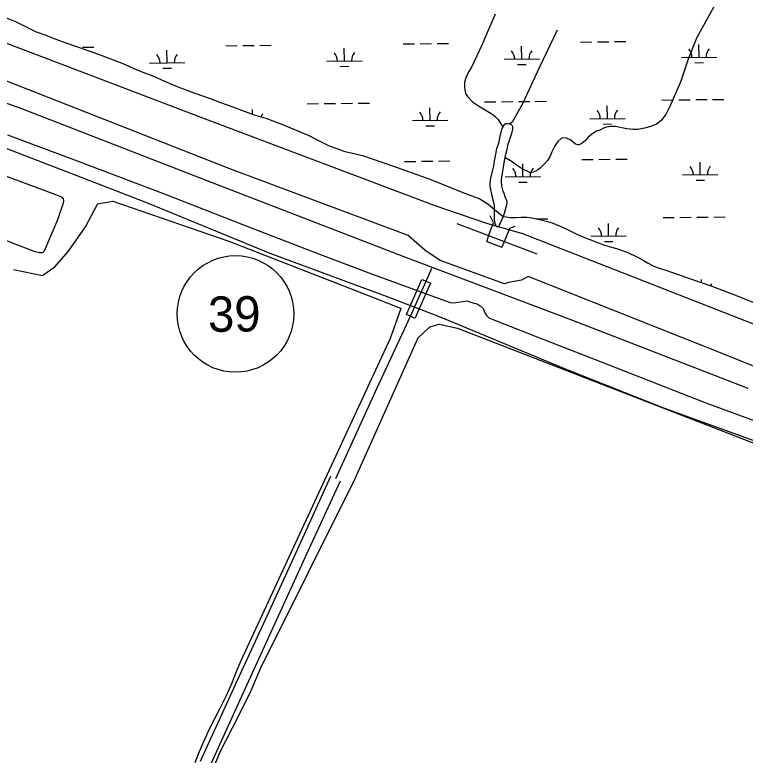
# Model space of a CAD drawing. Extents: x 3734862 to 3772949, y 391520 to 417239.
# Drawn here: x 3742033 to 3744100, y 410402 to 412498 of the extents above; entities that cross this region are included whole.
import ezdxf

# ---------------------------------------------------------------- set-up
doc = ezdxf.new("R2010")
doc.units = 0
for name, color, linetype in [('V-BRDG-OTLN', 7, 'Continuous'), ('V-LEVE-TOET', 7, 'Continuous'), ('V-ROAD-CNTR', 7, 'Continuous'), ('V-ROAD-IDEN', 7, 'Continuous'), ('V-RRAP-FSHR', 7, 'Continuous'), ('V-SITE-VEGE', 7, 'Continuous'), ('V-TOPO-SHOR', 7, 'Continuous'), ('V-TRAN-LOCK', 7, 'Continuous'), ('V-WETL-SWMP', 7, 'Continuous')]:
    doc.layers.add(name, color=color, linetype=linetype)

msp = doc.modelspace()

# ---------------------------------------------------------------- linework, layer by layer
at = {"layer": 'V-BRDG-OTLN'}
msp.add_line((3743152.4, 411644.3), (3743197.4, 411743.5), dxfattribs=at)
msp.add_lwpolyline([(3743165.3, 411638.4), (3743152.4, 411644.3), (3743141.2, 411649.6), (3743184.9, 411748.9), (3743197.4, 411743.5), (3743209.5, 411738.2)], close=True, dxfattribs=at)
at = {"layer": 'V-LEVE-TOET'}
msp.add_line((3743367.5, 411908.1), (3743469.8, 411878.6), dxfattribs=at)
for points in [[(3738852.9, 413396.4), (3739138.4, 413315.6), (3740264.7, 412984.9), (3741306.9, 412677.6), (3741416.7, 412646.4), (3741439.2, 412637.7), (3741731.3, 412522.7), (3742578.6, 412200.2), (3743221.3, 411958.2), (3743367.5, 411908.1)], [(3744926.8, 411188.3), (3744890.4, 411207.3), (3744850.8, 411205.9), (3744810.7, 411224.9), (3744044.1, 411535), (3743485.6, 411757.3), (3743467, 411746.5), (3743430.2, 411739.8), (3743419.1, 411736.3), (3743236.4, 411801.8), (3743192.8, 411831.9), (3743145.7, 411873.1), (3742641.7, 412061.3), (3741586.5, 412475.4), (3741466, 412517.8), (3741404.7, 412536.6), (3741298.7, 412571.4), (3740527, 412789.8), (3739719, 413038.2), (3738899.6, 413268.3), (3738854.4, 413281.1)], [(3743469.8, 411878.6), (3744276.8, 411562.5), (3744864.5, 411325.1), (3744898.6, 411320.1), (3745007.8, 411297.3)]]:
    msp.add_lwpolyline(points, dxfattribs=at)
at = {"layer": 'V-ROAD-CNTR'}
for points in [[(3738852, 413216.3), (3739597.6, 412997), (3740128.2, 412846.1), (3740911.5, 412622.8), (3741371.7, 412476), (3742051.4, 412232), (3742605.7, 412017.1), (3743130.7, 411814.9), (3743608.3, 411634.1), (3744107.4, 411440.8)], [(3742941.2, 411185.1), (3742994, 411301.1), (3743064.2, 411454.1), (3743135.4, 411608.1), (3743152.4, 411644.3), (3743197.4, 411743.5), (3743213.2, 411780.1)], [(3742557.9, 410384.9), (3742657.3, 410602.2), (3742747.4, 410798.6), (3742838, 410996.9), (3742927.5, 411191.4)], [(3742585.2, 410372.5), (3742684.6, 410589.7), (3742774.6, 410786.1), (3742865.3, 410984.4), (3742954.8, 411178.9)]]:
    msp.add_lwpolyline(points, dxfattribs=at)
at = {"layer": 'V-ROAD-IDEN'}
msp.add_circle((3742657.4, 411650.9), 165, dxfattribs=at)
msp.add_circle((3742657.4, 411650.9), 165, dxfattribs=at)
at = {"layer": 'V-RRAP-FSHR'}
for points in [[(3743368.4, 411856.4), (3743375.5, 411876.7), (3743387.2, 411909.6), (3743378.2, 411928.5)], [(3743283.6, 411907.2), (3743510.1, 411820.7)], [(3743448.3, 411898.2), (3743432.7, 411892.6), (3743419.3, 411859.7), (3743411.2, 411840.1)]]:
    msp.add_lwpolyline(points, dxfattribs=at)
at = {"layer": 'V-SITE-VEGE'}
for points in [[(3742029.4, 411776.3), (3742111.1, 411760.1), (3742111.8, 411760.3), (3742146.1, 411784.4), (3742184.9, 411828.9), (3742232.3, 411897.6), (3742266.6, 411962), (3742267.1, 411962.5), (3742309.7, 411970.5), (3742310.2, 411970.4), (3742638, 411857.2), (3743052.2, 411695.3), (3743124.7, 411667.3), (3743125.2, 411666.9), (3743125.3, 411666.1), (3743095.4, 411581.9), (3742672.5, 410669.4)], [(3742597, 410370), (3742612.5, 410409.4), (3742667.1, 410514.2), (3742701.8, 410585.6), (3742729, 410649), (3742996.1, 411185.3), (3743173, 411581.8), (3743173.2, 411582.1), (3743207.4, 411614.2), (3743207.8, 411614.4), (3743233.2, 411622.4), (3743233.8, 411622.4), (3743285.3, 411610.3), (3746427, 410392)], [(3742672.5, 410669.4), (3742661.4, 410642.5), (3742652.4, 410621.5), (3742645.9, 410604.5), (3742631.1, 410570.3), (3742624.3, 410556.6), (3742611.7, 410532.4), (3742583.8, 410477.3), (3742575.1, 410459.2), (3742565.5, 410437.9), (3742551.9, 410405.4), (3742541.8, 410380.5)]]:
    msp.add_lwpolyline(points, dxfattribs=at)
at = {"layer": 'V-TOPO-SHOR'}
for points in [[(3738856.9, 413083.7), (3739161.6, 412995.9), (3739452.4, 412912.1), (3739705.5, 412839.6), (3740003.1, 412755.6), (3740393.5, 412645.8), (3740671.5, 412564.1), (3740972.5, 412480.8), (3741257.8, 412388.9), (3741438.8, 412334.5), (3741752.7, 412215.1), (3741995.4, 412125.2), (3742217.9, 412039.1), (3742410.1, 411964.3), (3742754, 411823.4), (3743083.5, 411701.7), (3743238, 411641.7), (3743590.1, 411495.3), (3743868.3, 411385.2), (3744209.8, 411261.9), (3744443, 411170.9), (3744579.1, 411127.5)], [(3744015.7, 412528.2), (3743963.1, 412433.4), (3743938.8, 412371.6), (3743917.3, 412310.1), (3743909.1, 412290.2), (3743895.7, 412259.5), (3743886.3, 412238), (3743875.2, 412215.6), (3743861.2, 412197.5), (3743849.3, 412187.7), (3743833.1, 412181.1), (3743814.7, 412176.3), (3743795.6, 412173.3), (3743782.1, 412172.7), (3743765.1, 412174.6), (3743750.3, 412177.8), (3743742.7, 412179.5), (3743731.6, 412181.2), (3743718.3, 412181.2), (3743707.7, 412180), (3743698.8, 412176.5), (3743688.2, 412171.5), (3743679.3, 412167.8), (3743665.9, 412159.8), (3743654.9, 412150), (3743648.6, 412142.6), (3743638.4, 412134.2), (3743630.1, 412129.6), (3743626.4, 412129.1), (3743620, 412131.2), (3743611.7, 412137.6), (3743604.3, 412143.4), (3743593.7, 412148.4), (3743586.6, 412149.1), (3743579.2, 412147.5), (3743569.4, 412138.8), (3743559.8, 412124.9), (3743552.9, 412109.9), (3743546.6, 412095.8), (3743540.4, 412085.3), (3743532, 412076.2), (3743519.7, 412063.9), (3743512.9, 412059.1), (3743506.6, 412055.1), (3743499.5, 412052.1), (3743495.8, 412051.2), (3743490.3, 412051.7), (3743468.4, 412061.4), (3743448.4, 412075.2), (3743437.6, 412083.3), (3743419.6, 412093.7)], [(3743392.5, 412499.4), (3743370.5, 412449), (3743355.2, 412413.8), (3743324.8, 412349.4), (3743314.9, 412332.7), (3743308, 412316.1), (3743305.8, 412305.6), (3743305.2, 412290.9), (3743308.3, 412275.2), (3743314.2, 412265.9), (3743328.1, 412251.5), (3743345.1, 412239.7), (3743359.1, 412231.2), (3743385.3, 412215.5), (3743392.9, 412209.1), (3743401, 412200.8), (3743414.4, 412180)], [(3743567.3, 412453.7), (3743516.8, 412347.1), (3743469.9, 412245.5), (3743440.7, 412193.9), (3743433.9, 412188.5)], [(3743390.2, 411946.1), (3743390, 411958.1), (3743387.9, 411970.1), (3743385, 411980.2), (3743382.4, 411990.2), (3743380, 412003.4), (3743378.5, 412012.7), (3743378.4, 412020.9), (3743379.1, 412029.8), (3743380.8, 412039.8), (3743388.3, 412068.8), (3743390.4, 412083.8), (3743392.8, 412097.8), (3743394.7, 412109), (3743397.4, 412119.4), (3743401, 412129.3), (3743403.8, 412138.1), (3743405.8, 412148.6), (3743407.4, 412158.9), (3743409.2, 412165.5), (3743411.4, 412172.7), (3743414.4, 412180), (3743416.7, 412184.4), (3743419.6, 412187.9), (3743422.7, 412189.6), (3743425.2, 412190), (3743429.4, 412189.6), (3743433.9, 412188.5), (3743437.2, 412186.9), (3743440.1, 412184.5), (3743441.2, 412182.5), (3743441.6, 412179.2), (3743441.4, 412175), (3743438.6, 412161.5), (3743434.5, 412150), (3743430.6, 412138.5), (3743427.5, 412127.5), (3743424.9, 412116.6), (3743422.5, 412106.3), (3743419.6, 412093.7), (3743417.9, 412084), (3743416, 412071.7), (3743414.4, 412060.6), (3743411, 412042.3), (3743409, 412032.7), (3743409.1, 412024.4), (3743410, 412014.9), (3743411.1, 412009.1), (3743413.2, 412000.9), (3743416.4, 411992.9), (3743418.9, 411984.9), (3743422, 411977), (3743424.1, 411972.5), (3743425.1, 411968.6), (3743424.7, 411960.9), (3743423.8, 411955.8), (3743420.7, 411945.8), (3743417.8, 411935.6), (3743414.5, 411926.9), (3743405.5, 411906.2), (3743403.2, 411901.1), (3743401.3, 411897.9), (3743400, 411897), (3743397.3, 411897.8), (3743395.4, 411899.5), (3743393.6, 411904), (3743391.4, 411911), (3743390.2, 411919.2), (3743390.1, 411928.7), (3743390.2, 411946.1)], [(3742012.2, 412157.4), (3742216.5, 412081.7), (3742463.2, 411988.4), (3742701.8, 411894.6), (3742894.7, 411819.7), (3743042.6, 411764.6), (3743262.4, 411683.9), (3743269.8, 411682.4), (3743280.7, 411682.9), (3743294.9, 411685.4), (3743311.8, 411687.8), (3743329.3, 411682.8), (3743341.5, 411679.2), (3743349.5, 411674.3), (3743358.2, 411666.1), (3743363.4, 411653.8), (3743368, 411647), (3743374.6, 411640.1), (3743388.1, 411634.5), (3743513.1, 411585.1), (3743691.8, 411515.2), (3743988.2, 411399.5), (3744229.6, 411311)], [(3741973.8, 412053.2), (3742113.3, 412002.3), (3742160.3, 411984.2), (3742165.8, 411981.3), (3742170, 411976.6), (3742170.8, 411971), (3742169.8, 411964.4), (3742153.1, 411917.4), (3742115.6, 411828.7), (3742113.7, 411826.4), (3742112.3, 411825), (3742109.5, 411824.1), (3742102.4, 411823.8), (3742089.9, 411826.8), (3741949.4, 411880.5)]]:
    msp.add_lwpolyline(points, dxfattribs=at)
at = {"layer": 'V-TRAN-LOCK'}
msp.add_line((3743368.4, 411856.4), (3743411.2, 411840.1), dxfattribs=at)
at = {"layer": 'V-WETL-SWMP'}
for p, q in [((3742006.6, 412489.8), (3742036.5, 412477.8)), ((3742036.5, 412477.8), (3742092.8, 412449.7)), ((3742092.8, 412449.7), (3742120.3, 412439.6)), ((3742120.3, 412439.6), (3742146.3, 412429.6)), ((3742146.3, 412429.6), (3742179.8, 412417.7)), ((3742179.8, 412417.7), (3742213.1, 412405.6)), ((3743132.2, 412415.1), (3743164.2, 412415.5)), ((3743180.2, 412415.7), (3743212.2, 412416)), ((3743228.2, 412416.2), (3743260.2, 412416.5)), ((3743634.1, 412420.4), (3743666.1, 412420.8)), ((3743682.1, 412421), (3743714.1, 412421.3)), ((3743730.1, 412421.5), (3743762.1, 412421.8)), ((3743969.4, 412377.6), (3743969, 412413.6)), ((3742213.1, 412405.6), (3742245.2, 412394.5)), ((3742224.4, 412405.6), (3742256.4, 412405.9)), ((3742245.2, 412394.5), (3742278.6, 412382.8)), ((3742463.8, 412361.7), (3742463.4, 412397.7)), ((3742630.3, 412409.8), (3742662.3, 412410.2)), ((3742678.3, 412410.4), (3742710.3, 412410.7)), ((3742726.3, 412410.9), (3742758.3, 412411.2)), ((3742965.6, 412367), (3742965.3, 412403)), ((3743467.5, 412372.3), (3743467.1, 412408.3)), ((3742278.6, 412382.8), (3742343, 412357.7)), ((3743417.5, 412371.7), (3743517.5, 412372.8)), ((3743919.4, 412377), (3744019.4, 412378.1)), ((3742343, 412357.7), (3742369.2, 412345.5)), ((3742413.8, 412361.1), (3742513.8, 412362.2)), ((3742915.6, 412366.4), (3743015.6, 412367.5)), ((3742953.8, 412351.4), (3742977.8, 412351.7)), ((3743455.7, 412356.7), (3743479.7, 412357)), ((3743957.6, 412362), (3743981.6, 412362.3)), ((3742369.2, 412345.5), (3742395.3, 412335.5)), ((3742395.3, 412335.5), (3742422.9, 412324.5)), ((3742451.9, 412346.1), (3742475.9, 412346.4)), ((3742422.9, 412324.5), (3742456.1, 412309.5)), ((3742456.1, 412309.5), (3742489.4, 412295.8)), ((3742489.4, 412295.8), (3742532, 412279.9)), ((3742532, 412279.9), (3742593.1, 412257.7)), ((3742593.1, 412257.7), (3742615.2, 412249.7)), ((3742615.2, 412249.7), (3742649.7, 412236.8)), ((3742860.1, 412245.8), (3742892.1, 412246.1)), ((3742908.1, 412246.3), (3742940.1, 412246.6)), ((3742956.1, 412246.8), (3742988.1, 412247.1)), ((3743004.1, 412247.3), (3743036.1, 412247.6)), ((3743361.9, 412251.1), (3743393.9, 412251.4)), ((3743409.9, 412251.6), (3743441.9, 412251.9)), ((3743457.9, 412252.1), (3743489.9, 412252.4)), ((3743505.9, 412252.6), (3743537.9, 412252.9)), ((3743863.8, 412256.4), (3743895.8, 412256.7)), ((3743911.8, 412256.9), (3743943.8, 412257.2)), ((3743959.8, 412257.4), (3743991.8, 412257.7)), ((3744007.8, 412257.9), (3744039.8, 412258.2)), ((3742649.7, 412236.8), (3742674.6, 412227.2)), ((3742674.6, 412227.2), (3742710, 412214.7)), ((3742705.8, 412216.2), (3742705.6, 412229.4)), ((3743207.9, 412198.7), (3743207.5, 412234.7)), ((3743709.8, 412204), (3743709.4, 412240)), ((3742710, 412214.7), (3742742.9, 412204.6)), ((3742742.9, 412204.6), (3742790.3, 412187.2)), ((3743659.8, 412203.5), (3743759.8, 412204.5)), ((3742790.3, 412187.2), (3742862.6, 412156.5)), ((3743157.9, 412198.2), (3743257.9, 412199.2)), ((3743196.1, 412183.1), (3743220.1, 412183.4)), ((3743697.9, 412188.4), (3743721.9, 412188.7)), ((3742862.6, 412156.5), (3742894.3, 412140.5)), ((3742894.3, 412140.5), (3742922.3, 412127.1)), ((3742922.3, 412127.1), (3742944.2, 412118.7)), ((3742944.2, 412118.7), (3742967.2, 412111.1)), ((3742967.2, 412111.1), (3742984.9, 412106.9)), ((3742984.9, 412106.9), (3743016.9, 412099.5)), ((3743016.9, 412099.5), (3743101.2, 412069.8)), ((3743135.7, 412082.5), (3743167.7, 412082.8)), ((3743183.7, 412083), (3743215.7, 412083.3)), ((3743231.7, 412083.5), (3743263.7, 412083.8)), ((3743637.6, 412087.8), (3743669.6, 412088.1)), ((3743685.6, 412088.3), (3743717.6, 412088.6)), ((3743733.6, 412088.8), (3743765.6, 412089.1)), ((3743972.9, 412044.9), (3743972.5, 412080.9)), ((3743101.2, 412069.8), (3743210.5, 412031.2)), ((3743471, 412039.6), (3743470.7, 412075.6)), ((3743421, 412039.1), (3743521, 412040.1)), ((3743922.9, 412044.4), (3744022.9, 412045.4)), ((3743210.5, 412031.2), (3743300.7, 411994.7)), ((3743459.2, 412024), (3743483.2, 412024.3)), ((3743961.1, 412029.4), (3743985.1, 412029.6)), ((3743300.7, 411994.7), (3743349.2, 411976.7)), ((3743349.2, 411976.7), (3743371.9, 411962.3)), ((3743371.9, 411962.3), (3743390.2, 411946.1)), ((3743390.2, 411946.1), (3743414.5, 411927)), ((3743414.5, 411927), (3743436.2, 411924)), ((3743436.2, 411924), (3743451.6, 411924)), ((3743451.6, 411924), (3743465.6, 411925.2)), ((3743465.6, 411925.2), (3743483, 411924.8)), ((3743483, 411924.8), (3743495.8, 411923.2)), ((3743495.8, 411923.2), (3743509.5, 411919.7)), ((3743509.5, 411919.9), (3743541.5, 411920.3)), ((3743509.5, 411919.7), (3743525, 411915.9)), ((3743525, 411915.9), (3743536.9, 411913.8)), ((3743536.9, 411913.8), (3743553.1, 411908.6)), ((3743867.3, 411923.7), (3743899.3, 411924.1)), ((3743915.3, 411924.2), (3743947.3, 411924.6)), ((3743963.3, 411924.7), (3743995.3, 411925.1)), ((3744011.3, 411925.2), (3744043.3, 411925.6)), ((3743553.1, 411908.6), (3743576.4, 411899.5)), ((3743576.4, 411899.5), (3743594.7, 411891.2)), ((3743594.7, 411891.2), (3743624.8, 411875.7)), ((3743713.3, 411871.3), (3743712.9, 411907.3)), ((3743624.8, 411875.7), (3743640.2, 411869.1)), ((3743640.2, 411869.1), (3743660.5, 411861.4)), ((3743663.3, 411870.8), (3743763.3, 411871.9)), ((3743660.5, 411861.4), (3743682, 411852.7)), ((3743682, 411852.7), (3743701.7, 411845.3)), ((3743701.5, 411855.8), (3743725.5, 411856)), ((3743701.7, 411845.3), (3743721.4, 411839.7)), ((3743721.4, 411839.7), (3743735.4, 411836)), ((3743735.4, 411836), (3743763, 411827)), ((3743763, 411827), (3743775.4, 411821.4)), ((3743775.4, 411821.4), (3743785.3, 411816.6)), ((3743785.3, 411816.6), (3743799.2, 411809.7)), ((3743799.2, 411809.7), (3743812.5, 411802.2)), ((3743812.5, 411802.2), (3743823.6, 411795.4)), ((3743823.6, 411795.4), (3743839.2, 411787)), ((3743839.2, 411787), (3743853.6, 411781.1)), ((3743853.6, 411781.1), (3743875.6, 411774.4)), ((3743875.6, 411774.4), (3743947.6, 411749.8)), ((3743947.6, 411749.8), (3744005.3, 411729.7)), ((3743976.1, 411739.9), (3743976, 411748.3)), ((3744005.3, 411729.7), (3744077.5, 411701.9)), ((3744077.5, 411701.9), (3744165.4, 411667))]:
    msp.add_line(p, q, dxfattribs=at)
for centre, start, end in [((3743412.3, 412372.1), 359.8334, 41.377), ((3743522.8, 412373.3), 139.8333, 181.377), ((3743914.1, 412377.4), 359.8334, 41.377), ((3744024.6, 412378.6), 139.8333, 181.377), ((3742408.5, 412361.5), 359.8334, 41.377), ((3742519, 412362.7), 139.8333, 181.377), ((3742910.4, 412366.8), 359.8334, 41.377), ((3743020.9, 412368), 139.8333, 181.377), ((3743654.5, 412203.9), 359.8334, 41.377), ((3743765, 412205.1), 139.8333, 181.377), ((3742761.3, 412194.5), 139.8333, 155.8978), ((3743152.7, 412198.6), 359.8334, 41.377), ((3743263.1, 412199.8), 139.8333, 181.377), ((3743415.8, 412039.5), 359.8334, 41.377), ((3743526.3, 412040.7), 139.8333, 181.377), ((3743917.7, 412044.8), 359.8334, 41.377), ((3744028.1, 412046), 139.8333, 181.377), ((3743658.1, 411871.2), 359.8334, 41.377), ((3743768.5, 411872.4), 139.8333, 181.377), ((3744031.7, 411713.3), 139.8333, 149.6717)]:
    msp.add_arc(centre, 35.2, start, end, dxfattribs=at)

# ---------------------------------------------------------------- texts
at = {"layer": 'V-ROAD-IDEN'}
msp.add_text('39', height=100, rotation=0.6052, dxfattribs=at).set_placement((3742580, 411600.1))

doc.saveas('drawing.dxf')
